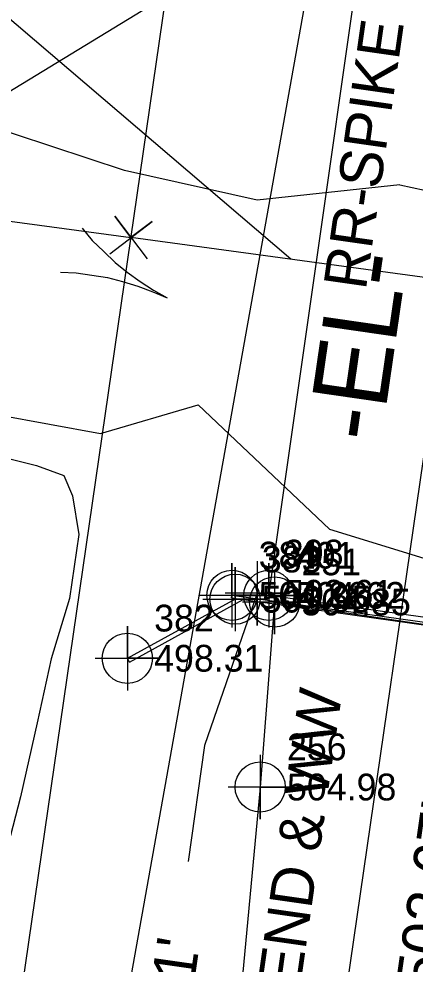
# Model space of a CAD drawing. Extents: x 1698744 to 1699848, y 707609 to 709748.
# Drawn here: x 1699360.1 to 1699397.1, y 708679.7 to 708768 of the extents above; entities that cross this region are included whole.
import ezdxf

# ---------------------------------------------------------------- set-up
doc = ezdxf.new("R2010")
doc.units = 0
for name, color, linetype in [('Exist Horizontal Alignment', 7, 'Continuous'), ('Exist Horizontal Alignment Direction Label', 7, 'Continuous'), ('Exist Horizontal Baseline Alignment', 7, 'Continuous'), ('Exist Hydro Jurisdictional Stream or Body of Water', 7, 'Continuous'), ('Exist Hydro Jurisdictional Stream or Body of Water Leader', 7, 'Continuous'), ('Exist Hydro Stream Flow Arrow CELL', 7, 'Continuous'), ('Exist Property Corner CELL', 7, 'Continuous'), ('Exist Property Iron Pin Text', 7, 'Continuous'), ('Exist Property Line', 7, 'Continuous'), ('Exist Property Tie Line', 7, 'Continuous'), ('Exist Property Tie Line Leader', 7, 'Continuous'), ('Exist Right of Way Line', 7, 'Continuous'), ('Exist Structure Major Bridge Seat Cogo Elevation', 7, 'Continuous'), ('Exist Structure Major Bridge Seat Cogo Number', 7, 'Continuous'), ('Exist Structure Major Bridge Seat Cogo Point CELL', 7, 'Continuous'), ('Exist Structure Major Bridge Seat Top Elevation', 7, 'Continuous'), ('Exist Structure Major Bridge Topo Leader', 7, 'Continuous'), ('Exist Structure Major Bridge WW', 7, 'Continuous'), ('Exist Structure Major Bridge WW Cogo Elevation', 7, 'Continuous'), ('Exist Structure Major Bridge WW Cogo Number', 7, 'Continuous'), ('Exist Structure Major Bridge WW Cogo Point CELL', 7, 'Continuous'), ('Exist Structure Major Bridge WW Text', 7, 'Continuous'), ('Exist Structure Major Deck Tunnel Box Culvert', 7, 'Continuous'), ('Exist Structure Major Deck Tunnel Box Culvert Cogo Elevation', 7, 'Continuous'), ('Exist Structure Major Deck Tunnel Box Culvert Cogo Number', 7, 'Continuous'), ('Exist Structure Major Deck Tunnel Box Culvert Cogo Point CELL', 7, 'Continuous'), ('Exist Vegetation Woods Line', 7, 'Continuous'), ('Sheet Border Standard 30in CELL', 7, 'Continuous'), ('Sheet Data Field CELL', 7, 'Continuous'), ('Sheet Plot Border Inside CELL', 7, 'Continuous'), ('Sheet Sticker Preliminary CELL', 7, 'Continuous')]:
    doc.layers.add(name, color=color, linetype=linetype)

# ---------------------------------------------------------------- blocks, each defined once
blk = doc.blocks.new('EXIST HYDRO STREAM FLOW ARROW')
at = {"layer": 'Exist Hydro Stream Flow Arrow CELL'}
blk.add_line((0, 0), (0, 0), dxfattribs=at)
for points in [[(-0.1, 0.04575), (-0.07325, 0.03375), (-0.04475, 0.0245), (-0.0165, 0.01575), (0.01175, 0.0095), (0.041, 0.00475), (0.07075, 0.0015), (0.1, 0)], [(-0.1, -0.04575), (-0.07325, -0.03375), (-0.04475, -0.0245), (-0.0165, -0.01575), (0.01175, -0.0095), (0.041, -0.00475), (0.07075, -0.0015), (0.1, 0)]]:
    blk.add_lwpolyline(points, dxfattribs=at)

msp = doc.modelspace()

# ---------------------------------------------------------------- linework, layer by layer
at = {"layer": 'Exist Horizontal Alignment'}
msp.add_line((1699389.789, 708670.951), (1699406.719, 708787.864), dxfattribs=at)
at = {"layer": 'Exist Horizontal Baseline Alignment'}
msp.add_line((1699300.216, 708284.802), (1699395.766, 708819.437), dxfattribs=at)
at = {"layer": 'Exist Hydro Jurisdictional Stream or Body of Water'}
for p, q in [((1699395.686, 708752.496), (1699404.737, 708750.562)), ((1699389.13, 708720.332), (1699411.615, 708713.364))]:
    msp.add_line(p, q, dxfattribs=at)
for points in [[(1699395.686, 708752.496), (1699382.375, 708751.073), (1699369.975, 708753.84), (1699356.367, 708758.314), (1699340.586, 708761.047), (1699335.852, 708767.509), (1699327.196, 708775.23), (1699315.596, 708778.972), (1699296.289, 708787.348), (1699277.666, 708794.772)], [(1699278.242, 708771.371), (1699294.363, 708763.356), (1699313.418, 708754.348), (1699332.926, 708742.733), (1699338.057, 708739.118), (1699348.726, 708734.996), (1699358.147, 708731.016), (1699367.727, 708729.248), (1699376.832, 708731.945), (1699389.13, 708720.332)]]:
    msp.add_lwpolyline(points, dxfattribs=at)
at = {"layer": 'Exist Hydro Jurisdictional Stream or Body of Water Leader'}
msp.add_lwpolyline([(1699384.184, 708776.436), (1699327.245, 708741.707), (1699324.146, 708716.836)], dxfattribs=at)
at = {"layer": 'Exist Property Corner CELL'}
msp.add_line((1699370.571, 708747.567), (1699370.571, 708747.567), dxfattribs=at)
msp.add_lwpolyline([(1699368.581, 708746.054), (1699372.561, 708749.08), (1699370.571, 708747.567), (1699369.058, 708749.557), (1699372.084, 708745.577)], dxfattribs=at)
at = {"layer": 'Exist Property Line'}
msp.add_line((1699346.996, 708750.778), (1699370.571, 708747.567), dxfattribs=at)
at = {"layer": 'Exist Property Tie Line'}
msp.add_line((1699402.638, 708743.2), (1699370.571, 708747.567), dxfattribs=at)
at = {"layer": 'Exist Property Tie Line Leader'}
msp.add_lwpolyline([(1699385.495, 708745.545), (1699351.901, 708774.28)], dxfattribs=at)
at = {"layer": 'Exist Right of Way Line'}
msp.add_line((1699360.099, 708675.25), (1699377.029, 708792.163), dxfattribs=at)
at = {"layer": 'Exist Structure Major Bridge Seat Cogo Point CELL'}
msp.add_lwpolyline([(1699382.357, 708717.335), (1699382.357, 708711.335), (1699382.357, 708714.335), (1699385.357, 708714.335), (1699379.357, 708714.335)], dxfattribs=at)
at = {"layer": 'Exist Structure Major Bridge Topo Leader'}
msp.add_lwpolyline([(1699382.357, 708714.335), (1699377.451, 708700.124), (1699375.902, 708689.275)], dxfattribs=at)
at = {"layer": 'Exist Structure Major Bridge WW'}
for p, q in [((1699370.231, 708708.261), (1699380.4, 708713.837)), ((1699379.966, 708713.898), (1699380.001, 708714.145)), ((1699370.424, 708707.91), (1699381.062, 708713.744)), ((1699370.424, 708707.91), (1699370.231, 708708.261))]:
    msp.add_line(p, q, dxfattribs=at)
for points in [[(1699379.966, 708713.898), (1699411.88, 708709.422)], [(1699380.001, 708714.145), (1699411.573, 708709.718), (1699420.253, 708701.373)]]:
    msp.add_lwpolyline(points, dxfattribs=at)
at = {"layer": 'Exist Structure Major Bridge WW Cogo Point CELL'}
for points in [[(1699377.001, 708714.145), (1699383.001, 708714.145), (1699380.001, 708714.145), (1699380.001, 708717.145), (1699380.001, 708711.145)], [(1699377.295, 708713.78), (1699383.295, 708713.78), (1699380.295, 708713.78), (1699380.295, 708716.78), (1699380.295, 708710.78)], [(1699367.231, 708708.261), (1699373.231, 708708.261), (1699370.231, 708708.261), (1699370.231, 708711.261), (1699370.231, 708705.261)]]:
    msp.add_lwpolyline(points, dxfattribs=at)
for centre in [(1699380.001, 708714.145), (1699380.295, 708713.78), (1699370.231, 708708.261)]:
    msp.add_circle(centre, 2.344, dxfattribs=at)
at = {"layer": 'Exist Structure Major Deck Tunnel Box Culvert'}
msp.add_lwpolyline([(1699408.244, 708710.627), (1699383.452, 708714.132), (1699396.13, 708802.924), (1699420.914, 708799.24)], dxfattribs=at)
at = {"layer": 'Exist Structure Major Deck Tunnel Box Culvert Cogo Point CELL'}
msp.add_lwpolyline([(1699380.452, 708714.132), (1699386.452, 708714.132), (1699383.452, 708714.132), (1699383.452, 708717.132), (1699383.452, 708711.132)], dxfattribs=at)
msp.add_circle((1699383.452, 708714.132), 2.344, dxfattribs=at)
at = {"layer": 'Exist Vegetation Woods Line'}
msp.add_lwpolyline([(1699357.605, 708727.288), (1699361.744, 708726.273), (1699364.305, 708725.347), (1699365.097, 708723.449), (1699365.705, 708719.809), (1699364.835, 708713.853), (1699363.106, 708708.207), (1699361.798, 708702.223), (1699360.239, 708695.323), (1699358.337, 708687.967)], dxfattribs=at)
at = {"layer": 'Sheet Border Standard 30in CELL'}
for points in [[(1699383.991, 708716.515), (1699383.991, 708710.515), (1699383.991, 708713.515), (1699386.991, 708713.515), (1699380.991, 708713.515)], [(1699382.641, 708699.228), (1699382.641, 708693.228), (1699382.641, 708696.228), (1699385.641, 708696.228), (1699379.641, 708696.228)]]:
    msp.add_lwpolyline(points, dxfattribs=at)
for centre in [(1699383.991, 708713.515), (1699382.641, 708696.228)]:
    msp.add_circle(centre, 2.344, dxfattribs=at)
at = {"layer": 'Sheet Sticker Preliminary CELL'}
msp.add_line((1699383.991, 708713.515), (1699407.408, 708710.014), dxfattribs=at)
msp.add_lwpolyline([(1699383.991, 708713.515), (1699382.641, 708696.228), (1699380.52, 708673.605), (1699373.154, 708627.943), (1699365.751, 708590.104), (1699357.715, 708551.027), (1699349.2, 708514.918), (1699339.657, 708477.566), (1699327.767, 708437.186), (1699316.489, 708399.684), (1699302.08, 708358.616), (1699291.442, 708329.76), (1699274.251, 708290.347), (1699255.976, 708255.282)], dxfattribs=at)

# ---------------------------------------------------------------- block references
at = {"layer": 'Exist Hydro Stream Flow Arrow CELL', "xscale": 50, "yscale": 50.00000000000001, "rotation": -26.551909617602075}
msp.add_blockref('EXIST HYDRO STREAM FLOW ARROW', (1699369.475, 708744.16), dxfattribs=at)

# ---------------------------------------------------------------- texts
at = {"layer": 'Exist Horizontal Alignment Direction Label'}
msp.add_text('-EL-', height=7, rotation=81.76048, dxfattribs=at).set_placement((1699393.912, 708728.279))
at = {"layer": 'Exist Property Iron Pin Text'}
msp.add_text('RR-SPIKE', height=4, rotation=81.87382, dxfattribs=at).set_placement((1699392.506, 708742.584))
at = {"layer": 'Exist Structure Major Bridge Seat Cogo Elevation'}
msp.add_text('502.61', height=2.5, dxfattribs=at).set_placement((1699384.857, 708713.085))
at = {"layer": 'Exist Structure Major Bridge Seat Cogo Number'}
msp.add_text('398', height=2.5, dxfattribs=at).set_placement((1699384.857, 708716.835))
at = {"layer": 'Exist Structure Major Bridge Seat Top Elevation'}
msp.add_text("SEAT ELEV=502.61'", height=4, rotation=81.87382, dxfattribs=at).set_placement((1699370.02, 708632.683))
at = {"layer": 'Exist Structure Major Bridge Topo Leader'}
msp.add_text("SEAT ELEV=502.67'", height=4, rotation=81.87382, dxfattribs=at).set_placement((1699394.72, 708645.428))
at = {"layer": 'Exist Structure Major Bridge WW Cogo Elevation'}
for s, p in [('504.38', (1699382.501, 708712.895)), ('503.95', (1699382.795, 708712.53)), ('498.31', (1699372.731, 708707.011))]:
    msp.add_text(s, height=2.5, dxfattribs=at).set_placement(p)
at = {"layer": 'Exist Structure Major Bridge WW Cogo Number'}
for s, p in [('384', (1699382.501, 708716.645)), ('383', (1699382.795, 708716.28)), ('382', (1699372.731, 708710.761))]:
    msp.add_text(s, height=2.5, dxfattribs=at).set_placement(p)
at = {"layer": 'Exist Structure Major Bridge WW Text'}
msp.add_text('WOOD END & WW', height=4, rotation=81.87382, dxfattribs=at).set_placement((1699383.719, 708658.878))
at = {"layer": 'Exist Structure Major Deck Tunnel Box Culvert Cogo Elevation'}
msp.add_text('504.62', height=2.5, dxfattribs=at).set_placement((1699385.952, 708712.882))
at = {"layer": 'Exist Structure Major Deck Tunnel Box Culvert Cogo Number'}
msp.add_text('401', height=2.5, dxfattribs=at).set_placement((1699385.952, 708716.632))
at = {"layer": 'Sheet Data Field CELL'}
for s, p in [('251', (1699386.491, 708716.015)), ('256', (1699385.141, 708698.728))]:
    msp.add_text(s, height=2.5, dxfattribs=at).set_placement(p)
at = {"layer": 'Sheet Plot Border Inside CELL'}
for s, p in [('504.85', (1699386.491, 708712.265)), ('504.98', (1699385.141, 708694.978))]:
    msp.add_text(s, height=2.5, dxfattribs=at).set_placement(p)

doc.saveas('drawing.dxf')
